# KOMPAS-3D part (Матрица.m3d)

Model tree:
1. Копирование:3  (with: Операция вращения:1, Скругление:1, Скругление:2)  (labels: Копия тела : Тело 1; Копия грани : Копия тела : Тело 1; Копия грани : Операция вращения:1; Копия грани : Скругление:1)
2. Эскиз:2
3. Операция вращения:1
     Угол 1 = 360

Referenced files in C:\Users\andrey\Desktop\Заказ 1793547 (Черч)\Дет. 85\: Заготовка дет. 85.m3d
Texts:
  Копия тела : Тело 1
  Копия грани : Копия тела : Тело 1
  Копия грани : Операция вращения:1
  Копия грани : Скругление:1
  Копия грани : Скругление:2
